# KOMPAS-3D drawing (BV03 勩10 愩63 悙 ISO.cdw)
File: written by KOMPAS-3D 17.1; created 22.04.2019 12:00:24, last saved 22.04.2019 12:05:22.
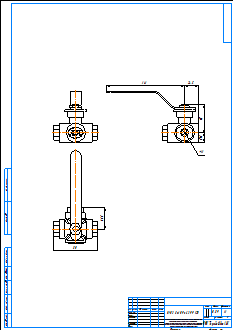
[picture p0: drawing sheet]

Sheet 1: A2, portrait

Title block, sheet 1: name: BV03 Ду10 Ру63 РР ISO; material: Внимание! Данный продукт является объектом авторского права ООО «Торговый Дом АДЛ». / Запрещается изменение, копирование, распространение / (в том числе путем копирования на другие сайты и ресурсы в Интернете) / или любое иное использование информации и объектов без предварительного / согласия правообладателя (ООО «Торговый Дом АДЛ»).; mass: 0,89; sheets: 1; organisation: ООО "Торговый дом АДЛ"; sheet format: A2

Views: Спереди 1, Проекционный вид 2, Проекционный вид 3
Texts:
  user
Dimensions and other numbers on the sheet: 80; 39,5; 51; 141; 24,5; 17,5; 11; 1:1; 1; 0,89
